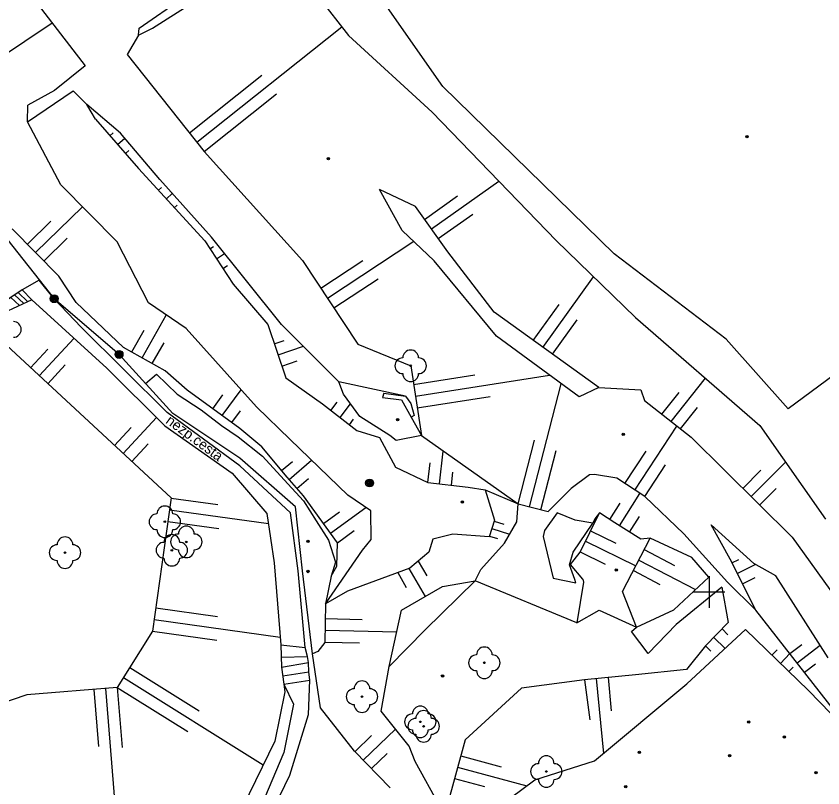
# Model space of a CAD drawing. Extents: x -639440 to -639026, y -1138850 to -1138262.
# Drawn here: x -639294 to -639242.8, y -1138562.4 to -1138513.4 of the extents above; entities that cross this region are included whole.
import ezdxf

# ---------------------------------------------------------------- set-up
doc = ezdxf.new("R2010")
doc.units = 0
for name, color, linetype in [('Vrstva 10', 7, 'Continuous'), ('Vrstva 11', 7, 'Continuous'), ('Vrstva 14', 7, 'Continuous'), ('Vrstva 15', 7, 'Continuous'), ('Vrstva 20', 7, 'Continuous'), ('Vrstva 22', 7, 'Continuous'), ('Vrstva 25', 7, 'Continuous'), ('Vrstva 40', 7, 'Continuous'), ('Vrstva 61', 7, 'Continuous'), ('Vrstva 7', 7, 'Continuous')]:
    doc.layers.add(name, color=color, linetype=linetype)

msp = doc.modelspace()

# ---------------------------------------------------------------- linework, layer by layer
at = {"layer": 'Vrstva 10'}
for p, q in [((-639266.91, -1138517.88), (-639273.38, -1138508.61)), ((-639256.02, -1138528.51), (-639266.91, -1138517.88)), ((-639248.91, -1138533.93), (-639256.02, -1138528.51)), ((-639244.97, -1138538.36), (-639248.91, -1138533.93)), ((-639239.11, -1138534.01), (-639244.97, -1138538.36))]:
    msp.add_line(p, q, dxfattribs=at)
at = {"layer": 'Vrstva 11'}
for p, q in [((-639286.2, -1138514.18), (-639283.12, -1138512.04)), ((-639285.35, -1138514.18), (-639282.84, -1138512.59)), ((-639286.24, -1138514.62), (-639285.35, -1138514.18)), ((-639286.24, -1138514.62), (-639286.2, -1138514.18)), ((-639289.62, -1138516.58), (-639291.57, -1138518.14)), ((-639291.57, -1138518.14), (-639293.27, -1138519.07)), ((-639288.97, -1138519.97), (-639289.51, -1138519.03)), ((-639287.37, -1138520.85), (-639289.51, -1138519.03)), ((-639284.89, -1138523.8), (-639287.37, -1138520.85)), ((-639281.6, -1138527.46), (-639284.89, -1138523.8)), ((-639291.3, -1138529.94), (-639294.25, -1138526.93)), ((-639277.16, -1138533), (-639281.6, -1138527.46)), ((-639292.54, -1138530.2), (-639293.63, -1138530.81)), ((-639291.59, -1138531.37), (-639292.54, -1138530.2)), ((-639290.2, -1138531.6), (-639291.3, -1138529.94)), ((-639293.63, -1138530.81), (-639295.29, -1138531.92)), ((-639294.104, -1138531.127), (-639293.523, -1138531.683)), ((-639293.261, -1138531.561), (-639293.867, -1138530.969)), ((-639293.63, -1138530.81), (-639293, -1138531.44)), ((-639293, -1138531.44), (-639294.83, -1138532.29)), ((-639293.784, -1138531.804), (-639294.341, -1138531.286)), ((-639289.87, -1138533.18), (-639291.59, -1138531.37)), ((-639287.18, -1138534.46), (-639290.2, -1138531.6)), ((-639284.41, -1138538.6), (-639289.87, -1138533.18)), ((-639273.52, -1138536.64), (-639277.16, -1138533)), ((-639284.54, -1138535.96), (-639287.18, -1138534.46)), ((-639283.14, -1138537.18), (-639284.54, -1138535.96)), ((-639279.8, -1138539.61), (-639283.14, -1138537.18)), ((-639270.66, -1138537.38), (-639270.75, -1138537.64)), ((-639270.66, -1138537.38), (-639269.29, -1138537.57)), ((-639270.75, -1138537.64), (-639269.54, -1138537.8)), ((-639269.54, -1138537.8), (-639268.91, -1138538.9)), ((-639269.29, -1138537.57), (-639268.94, -1138538.03)), ((-639268.94, -1138538.03), (-639268.72, -1138538.78)), ((-639279.8, -1138541.99), (-639284.41, -1138538.6)), ((-639268.72, -1138538.78), (-639268.91, -1138538.9)), ((-639268.91, -1138538.9), (-639268.26, -1138540.07)), ((-639278.41, -1138540.78), (-639279.8, -1138539.61)), ((-639276.8, -1138542.7), (-639278.41, -1138540.78)), ((-639276.59, -1138544.97), (-639279.8, -1138541.99)), ((-639275.76, -1138543.9), (-639276.8, -1138542.7)), ((-639273.6, -1138546.87), (-639275.76, -1138543.9)), ((-639276.09, -1138548.66), (-639276.59, -1138544.97)), ((-639258.19, -1138547.47), (-639256.97, -1138544.97)), ((-639273.64, -1138548.37), (-639273.6, -1138546.87)), ((-639258.81, -1138548.26), (-639258.19, -1138547.47)), ((-639275.66, -1138553.52), (-639276.09, -1138548.66)), ((-639273.99, -1138549), (-639273.64, -1138548.37)), ((-639258.02, -1138549.18), (-639258.81, -1138548.26)), ((-639249.19, -1138549.7), (-639252.09, -1138552.07)), ((-639254.93, -1138552.52), (-639254.62, -1138552.23)), ((-639252.09, -1138552.07), (-639253.86, -1138553.9)), ((-639253.86, -1138553.9), (-639254.93, -1138552.52)), ((-639277.19, -1138553.36), (-639275.66, -1138553.52)), ((-639277.19, -1138553.36), (-639277.16, -1138554.78)), ((-639275.51, -1138554.1), (-639275.66, -1138553.52)), ((-639277.174, -1138554.135), (-639275.51, -1138554.1)), ((-639275.44, -1138554.48), (-639275.51, -1138554.1)), ((-639277.16, -1138554.78), (-639275.44, -1138554.48)), ((-639277.16, -1138554.78), (-639277, -1138555.85)), ((-639275.42, -1138555.08), (-639275.44, -1138554.48)), ((-639277.078, -1138555.328), (-639275.42, -1138555.08)), ((-639275.36, -1138555.6), (-639275.42, -1138555.08)), ((-639277, -1138555.85), (-639275.36, -1138555.6)), ((-639277, -1138555.85), (-639276.39, -1138557.12)), ((-639275.43, -1138557.79), (-639275.36, -1138555.6)), ((-639276.39, -1138557.12), (-639277.01, -1138560.2)), ((-639276.62, -1138561.65), (-639275.43, -1138557.79)), ((-639277.01, -1138560.2), (-639278.62, -1138563.99)), ((-639278.5, -1138565.48), (-639276.62, -1138561.65))]:
    msp.add_line(p, q, dxfattribs=at)
at = {"layer": 'Vrstva 14'}
for p, q in [((-639277.59, -1138508.58), (-639272.91, -1138514.64)), ((-639293.74, -1138511.22), (-639289.62, -1138516.58)), ((-639286.24, -1138514.62), (-639286.96, -1138515.86)), ((-639272.91, -1138514.64), (-639267.58, -1138519.51)), ((-639286.96, -1138515.86), (-639282.07, -1138522.01)), ((-639293.29, -1138520.13), (-639290.39, -1138518.17)), ((-639290.39, -1138518.17), (-639289.51, -1138519.03)), ((-639293.29, -1138520.13), (-639293.27, -1138519.07)), ((-639288.97, -1138519.97), (-639286.24, -1138523.09)), ((-639267.58, -1138519.51), (-639259.71, -1138527.66)), ((-639291.17, -1138524.14), (-639293.29, -1138520.13)), ((-639282.07, -1138522.01), (-639275.81, -1138528.94)), ((-639286.24, -1138523.09), (-639282.03, -1138527.7)), ((-639287.59, -1138527.75), (-639291.17, -1138524.14)), ((-639268.65, -1138525.51), (-639270.94, -1138524.44)), ((-639269.49, -1138527.03), (-639270.94, -1138524.44)), ((-639266.6, -1138528.4), (-639268.65, -1138525.51)), ((-639267.45, -1138528.97), (-639269.49, -1138527.03)), ((-639259.71, -1138527.66), (-639254.67, -1138532.57)), ((-639285.61, -1138531.64), (-639287.59, -1138527.75)), ((-639282.03, -1138527.7), (-639280.22, -1138530.44)), ((-639263.66, -1138532.23), (-639266.6, -1138528.4)), ((-639275.81, -1138528.94), (-639272.31, -1138534.26)), ((-639263.5, -1138533.75), (-639267.45, -1138528.97)), ((-639280.22, -1138530.44), (-639278.03, -1138533.01)), ((-639293, -1138531.44), (-639288.24, -1138535.79)), ((-639283.2, -1138533.27), (-639285.61, -1138531.64)), ((-639257.01, -1138537.02), (-639263.66, -1138532.23)), ((-639296.56, -1138532.54), (-639284.16, -1138544.03)), ((-639254.67, -1138532.57), (-639246.79, -1138539.42)), ((-639278.75, -1138538.24), (-639283.2, -1138533.27)), ((-639278.03, -1138533.01), (-639276.87, -1138536.4)), ((-639258.25, -1138537.61), (-639263.5, -1138533.75)), ((-639272.31, -1138534.26), (-639268.95, -1138535.63)), ((-639288.24, -1138535.79), (-639284.57, -1138539.45)), ((-639268.95, -1138535.63), (-639268.26, -1138540.07)), ((-639285.78, -1138536.76), (-639285.1, -1138536.17)), ((-639285.1, -1138536.17), (-639283.77, -1138537.44)), ((-639276.87, -1138536.4), (-639274.56, -1138538.05)), ((-639269.29, -1138537.57), (-639273.52, -1138536.64)), ((-639273.22, -1138537.43), (-639273.52, -1138536.64)), ((-639257.01, -1138537.02), (-639258.25, -1138537.61)), ((-639257.01, -1138537.02), (-639254.34, -1138537.15)), ((-639254.34, -1138537.15), (-639254.1, -1138537.84)), ((-639283.77, -1138537.44), (-639282.26, -1138538.42)), ((-639272.18, -1138538.85), (-639273.22, -1138537.43)), ((-639254.1, -1138537.84), (-639251.15, -1138540.17)), ((-639282.26, -1138538.42), (-639280.96, -1138539.42)), ((-639276.61, -1138540.31), (-639278.75, -1138538.24)), ((-639274.56, -1138538.05), (-639272.36, -1138539.75)), ((-639270.27, -1138540.06), (-639272.18, -1138538.85)), ((-639284.57, -1138539.45), (-639280.28, -1138542.45)), ((-639280.96, -1138539.42), (-639279.91, -1138540.14)), ((-639246.79, -1138539.42), (-639242.6, -1138545.37)), ((-639272.36, -1138539.75), (-639270.94, -1138540.18)), ((-639279.91, -1138540.14), (-639278.37, -1138541.38)), ((-639272.95, -1138543.85), (-639276.61, -1138540.31)), ((-639270.94, -1138540.18), (-639269.92, -1138542.08)), ((-639269.88, -1138540.37), (-639270.27, -1138540.06)), ((-639268.26, -1138540.07), (-639269.88, -1138540.37)), ((-639268.26, -1138540.07), (-639262.13, -1138544.4)), ((-639251.15, -1138540.17), (-639244.72, -1138546.51)), ((-639278.37, -1138541.38), (-639276.99, -1138542.87)), ((-639280.28, -1138542.45), (-639278.08, -1138545.02)), ((-639269.92, -1138542.08), (-639267.86, -1138543.05)), ((-639257.27, -1138542.53), (-639257.59, -1138542.55)), ((-639255.86, -1138542.78), (-639257.27, -1138542.53)), ((-639276.99, -1138542.87), (-639275.75, -1138544.22)), ((-639257.59, -1138542.55), (-639258.77, -1138543.42)), ((-639254.09, -1138543.94), (-639255.86, -1138542.78)), ((-639267.86, -1138543.05), (-639265.29, -1138543.34)), ((-639265.29, -1138543.34), (-639264.23, -1138543.52)), ((-639264.23, -1138543.52), (-639262.13, -1138544.4)), ((-639264.23, -1138543.52), (-639263.63, -1138545.43)), ((-639258.77, -1138543.42), (-639260.23, -1138544.89)), ((-639284.16, -1138544.03), (-639285.34, -1138552.49)), ((-639271.48, -1138544.84), (-639272.95, -1138543.85)), ((-639251.61, -1138546.3), (-639254.09, -1138543.94)), ((-639275.75, -1138544.22), (-639274.96, -1138545.48)), ((-639262.22, -1138545.55), (-639262.13, -1138544.4)), ((-639262.13, -1138544.4), (-639260.23, -1138544.89)), ((-639278.08, -1138545.02), (-639277.63, -1138548.14)), ((-639271.45, -1138546.67), (-639271.48, -1138544.84)), ((-639259.64, -1138544.97), (-639260.45, -1138546.1)), ((-639258.5, -1138545.44), (-639259.64, -1138544.97)), ((-639256.97, -1138544.97), (-639257.26, -1138545.35)), ((-639255.99, -1138545.6), (-639256.97, -1138544.97)), ((-639274.96, -1138545.48), (-639274.18, -1138546.7)), ((-639263.63, -1138545.43), (-639263.97, -1138546.5)), ((-639263, -1138546.9), (-639262.22, -1138545.55)), ((-639257.39, -1138545.62), (-639258.5, -1138545.44)), ((-639257.26, -1138545.35), (-639257.39, -1138545.62)), ((-639254.34, -1138546.64), (-639255.99, -1138545.6)), ((-639260.45, -1138546.1), (-639260.53, -1138546.47)), ((-639258.63, -1138547.47), (-639257.39, -1138545.62)), ((-639247.17, -1138548.19), (-639249.87, -1138545.73)), ((-639248.67, -1138547.92), (-639249.87, -1138545.73)), ((-639266.27, -1138546.33), (-639267.54, -1138546.65)), ((-639263.97, -1138546.5), (-639266.27, -1138546.33)), ((-639260.53, -1138546.47), (-639259.9, -1138549.12)), ((-639255.5, -1138549.97), (-639253.74, -1138546.59)), ((-639253.74, -1138546.59), (-639254.34, -1138546.64)), ((-639251.09, -1138547.82), (-639253.74, -1138546.59)), ((-639248.83, -1138549.37), (-639251.61, -1138546.3)), ((-639244.72, -1138546.51), (-639240.23, -1138552.81)), ((-639274.18, -1138546.7), (-639273.73, -1138548.11)), ((-639272, -1138547.35), (-639271.45, -1138546.67)), ((-639267.54, -1138546.65), (-639267.8, -1138547.48)), ((-639264.49, -1138548.58), (-639263, -1138546.9)), ((-639274.35, -1138550.75), (-639272, -1138547.35)), ((-639267.8, -1138547.48), (-639269, -1138548.49)), ((-639258.87, -1138548.27), (-639258.63, -1138547.47)), ((-639277.63, -1138548.14), (-639277.19, -1138553.36)), ((-639273.73, -1138548.11), (-639273.99, -1138549)), ((-639250.02, -1138549.07), (-639251.09, -1138547.82)), ((-639247.03, -1138551.15), (-639248.67, -1138547.92)), ((-639269, -1138548.49), (-639272.96, -1138549.94)), ((-639264.85, -1138549.3), (-639264.49, -1138548.58)), ((-639258.52, -1138549.21), (-639258.87, -1138548.27)), ((-639245.76, -1138548.98), (-639247.17, -1138548.19)), ((-639273.99, -1138549), (-639274.35, -1138550.75)), ((-639259.9, -1138549.12), (-639258.46, -1138549.41)), ((-639258.02, -1138549.18), (-639257.97, -1138549.38)), ((-639252.23, -1138551.14), (-639250.02, -1138549.07)), ((-639242.44, -1138554.18), (-639245.76, -1138548.98)), ((-639269.54, -1138551.16), (-639266.93, -1138549.65)), ((-639268.03, -1138552.41), (-639264.85, -1138549.3)), ((-639266.93, -1138549.65), (-639264.85, -1138549.3)), ((-639258.39, -1138551.97), (-639264.85, -1138549.3)), ((-639258.46, -1138549.41), (-639258.52, -1138549.21)), ((-639257.97, -1138549.38), (-639258.39, -1138551.97)), ((-639249.19, -1138549.7), (-639248.78, -1138551.95)), ((-639247.03, -1138551.15), (-639248.83, -1138549.37)), ((-639272.96, -1138549.94), (-639274.35, -1138550.75)), ((-639254.62, -1138552.23), (-639255.5, -1138549.97)), ((-639274.35, -1138550.75), (-639274.41, -1138553.22)), ((-639270.31, -1138554.73), (-639269.54, -1138551.16)), ((-639258.39, -1138551.97), (-639256.98, -1138551.16)), ((-639256.98, -1138551.16), (-639254.62, -1138552.23)), ((-639254.62, -1138552.23), (-639252.23, -1138551.14)), ((-639240.47, -1138559.58), (-639247.03, -1138551.15)), ((-639248.78, -1138551.95), (-639250.23, -1138553.42)), ((-639285.34, -1138552.49), (-639287.58, -1138556.07)), ((-639270.31, -1138554.73), (-639268.03, -1138552.41)), ((-639251.41, -1138555.84), (-639247.68, -1138552.39)), ((-639247.68, -1138552.39), (-639243.69, -1138556.27)), ((-639274.41, -1138553.22), (-639274.84, -1138553.78)), ((-639274.84, -1138553.78), (-639275.18, -1138553.93)), ((-639250.23, -1138553.42), (-639251.43, -1138554.93)), ((-639270.83, -1138557.57), (-639270.31, -1138554.73)), ((-639254.67, -1138555.27), (-639257.91, -1138555.58)), ((-639251.43, -1138554.93), (-639254.67, -1138555.27)), ((-639277, -1138555.85), (-639276.95, -1138556.35)), ((-639257.91, -1138555.58), (-639261.92, -1138556.12)), ((-639257.28, -1138560.73), (-639251.41, -1138555.84)), ((-639287.58, -1138556.07), (-639293.32, -1138556.53)), ((-639276.95, -1138556.35), (-639277.58, -1138559.48)), ((-639261.92, -1138556.12), (-639265.5, -1138559.4)), ((-639243.69, -1138556.27), (-639240.47, -1138559.58)), ((-639293.32, -1138556.53), (-639301.59, -1138559.4)), ((-639269.05, -1138559.79), (-639270.83, -1138557.57)), ((-639265.5, -1138559.4), (-639266.8, -1138564.16)), ((-639277.58, -1138559.48), (-639279.72, -1138563.89)), ((-639268.66, -1138560.77), (-639269.05, -1138559.79)), ((-639266.8, -1138564.16), (-639268.66, -1138560.77)), ((-639261.06, -1138561.94), (-639257.28, -1138560.73)), ((-639263.82, -1138563.96), (-639261.06, -1138561.94))]:
    msp.add_line(p, q, dxfattribs=at)
at = {"layer": 'Vrstva 15'}
for p, q in [((-639299.041, -1138518.762), (-639291.724, -1138513.843)), ((-639282.537, -1138521.423), (-639273.327, -1138514.1)), ((-639283.004, -1138520.836), (-639278.394, -1138517.171)), ((-639282.07, -1138522.01), (-639277.465, -1138518.348)), ((-639288.054, -1138521.017), (-639287.837, -1138520.827)), ((-639287.56, -1138521.581), (-639287.096, -1138521.175)), ((-639287.066, -1138522.146), (-639286.84, -1138521.948)), ((-639267.636, -1138526.939), (-639263.345, -1138523.895)), ((-639284.971, -1138524.479), (-639284.781, -1138524.306)), ((-639284.466, -1138525.033), (-639284.09, -1138524.69)), ((-639268.07, -1138526.327), (-639265.971, -1138524.838)), ((-639292.767, -1138528.443), (-639289.793, -1138525.528)), ((-639283.96, -1138525.587), (-639283.774, -1138525.417)), ((-639267.202, -1138527.551), (-639265.01, -1138525.996)), ((-639293.292, -1138527.907), (-639291.807, -1138526.451)), ((-639292.242, -1138528.978), (-639290.754, -1138527.52)), ((-639281.7, -1138528.199), (-639281.474, -1138528.05)), ((-639274.24, -1138531.327), (-639268.761, -1138527.723)), ((-639281.287, -1138528.825), (-639280.776, -1138528.488)), ((-639274.652, -1138530.7), (-639271.986, -1138528.946)), ((-639280.874, -1138529.451), (-639280.589, -1138529.263)), ((-639273.827, -1138531.954), (-639271.015, -1138530.104)), ((-639260.563, -1138534.461), (-639257.333, -1138529.976)), ((-639261.172, -1138534.022), (-639259.524, -1138531.734)), ((-639286.011, -1138535.124), (-639284.469, -1138532.412)), ((-639259.955, -1138534.899), (-639258.372, -1138532.702)), ((-639286.663, -1138534.754), (-639285.878, -1138533.372)), ((-639292.54, -1138536.265), (-639290.33, -1138533.88)), ((-639285.359, -1138535.495), (-639284.602, -1138534.164)), ((-639277.612, -1138534.232), (-639276.984, -1138534.018)), ((-639293.091, -1138535.755), (-639291.987, -1138534.564)), ((-639277.369, -1138534.942), (-639275.767, -1138534.393)), ((-639277.126, -1138535.651), (-639276.151, -1138535.318)), ((-639291.99, -1138536.774), (-639290.883, -1138535.58)), ((-639268.766, -1138536.812), (-639264.873, -1138536.207)), ((-639268.651, -1138537.553), (-639260.128, -1138536.229)), ((-639261.404, -1138544.587), (-639259.388, -1138536.773)), ((-639252.41, -1138539.175), (-639250.237, -1138536.423)), ((-639280.916, -1138538.798), (-639279.721, -1138537.156)), ((-639252.999, -1138538.71), (-639251.901, -1138537.32)), ((-639281.522, -1138538.357), (-639280.877, -1138537.471)), ((-639268.536, -1138538.295), (-639263.906, -1138537.575)), ((-639274.027, -1138538.462), (-639273.625, -1138537.942)), ((-639273.434, -1138538.92), (-639272.764, -1138538.053)), ((-639251.822, -1138539.64), (-639250.746, -1138538.278)), ((-639287.214, -1138541.2), (-639285.101, -1138538.92)), ((-639280.309, -1138539.239), (-639279.759, -1138538.483)), ((-639272.841, -1138539.379), (-639272.572, -1138539.031)), ((-639254.718, -1138543.529), (-639252.05, -1138539.459)), ((-639287.764, -1138540.691), (-639286.698, -1138539.541)), ((-639262.13, -1138544.4), (-639261.085, -1138540.347)), ((-639286.663, -1138541.71), (-639285.616, -1138540.58)), ((-639267.114, -1138543.134), (-639266.878, -1138541.046)), ((-639260.677, -1138544.775), (-639259.707, -1138541.013)), ((-639255.345, -1138543.118), (-639253.993, -1138541.055)), ((-639277.152, -1138542.28), (-639276.462, -1138541.701)), ((-639276.668, -1138542.852), (-639275.251, -1138541.624)), ((-639267.859, -1138543.05), (-639267.718, -1138541.801)), ((-639254.09, -1138543.94), (-639252.775, -1138541.933)), ((-639247.322, -1138543.945), (-639245.153, -1138541.745)), ((-639266.369, -1138543.218), (-639266.274, -1138542.379)), ((-639247.856, -1138543.418), (-639246.724, -1138542.27)), ((-639276.177, -1138543.419), (-639275.443, -1138542.783)), ((-639246.788, -1138544.471), (-639245.751, -1138543.42)), ((-639284.16, -1138544.031), (-639281.189, -1138544.445)), ((-639255.682, -1138545.794), (-639254.389, -1138543.744)), ((-639256.314, -1138545.392), (-639255.656, -1138544.368)), ((-639284.264, -1138544.774), (-639277.989, -1138545.649)), ((-639274.483, -1138545.656), (-639273.469, -1138544.919)), ((-639274.042, -1138546.263), (-639271.794, -1138544.628)), ((-639284.367, -1138545.517), (-639281.123, -1138545.969)), ((-639263.65, -1138545.493), (-639263.032, -1138545.689)), ((-639255.047, -1138546.194), (-639254.424, -1138545.205)), ((-639273.6, -1138546.869), (-639272.536, -1138546.095)), ((-639263.801, -1138545.969), (-639262.67, -1138546.329)), ((-639257.525, -1138546.107), (-639255.915, -1138546.892)), ((-639263.953, -1138546.446), (-639263.439, -1138546.609)), ((-639257.854, -1138546.781), (-639254.653, -1138548.343)), ((-639258.182, -1138547.455), (-639256.591, -1138548.231)), ((-639254.115, -1138547.309), (-639252.195, -1138548.309)), ((-639268.466, -1138548.04), (-639267.924, -1138548.976)), ((-639254.461, -1138547.975), (-639250.855, -1138549.852)), ((-639248.55, -1138548.156), (-639248.119, -1138547.937)), ((-639269.06, -1138548.512), (-639268.032, -1138550.288)), ((-639254.807, -1138548.64), (-639253.121, -1138549.518)), ((-639248.211, -1138548.825), (-639247.071, -1138548.246)), ((-639269.775, -1138548.774), (-639269.228, -1138549.718)), ((-639247.871, -1138549.493), (-639247.077, -1138549.09)), ((-639285.133, -1138551.004), (-639281.215, -1138551.551)), ((-639285.236, -1138551.747), (-639277.232, -1138552.864)), ((-639274.373, -1138551.684), (-639272.025, -1138551.741)), ((-639285.34, -1138552.49), (-639281.262, -1138553.059)), ((-639274.391, -1138552.434), (-639269.839, -1138552.544)), ((-639249.177, -1138552.352), (-639248.805, -1138552.719)), ((-639274.409, -1138553.183), (-639272.204, -1138553.237)), ((-639249.703, -1138552.886), (-639248.984, -1138553.596)), ((-639250.23, -1138553.42), (-639249.882, -1138553.763)), ((-639246.011, -1138554.013), (-639245.675, -1138553.668)), ((-639244.875, -1138553.92), (-639244.117, -1138553.33)), ((-639244.414, -1138554.512), (-639242.954, -1138553.375)), ((-639245.473, -1138554.536), (-639244.874, -1138553.92)), ((-639286.784, -1138554.798), (-639282.383, -1138557.553)), ((-639244.936, -1138555.059), (-639244.673, -1138554.788)), ((-639243.953, -1138555.104), (-639243.251, -1138554.557)), ((-639287.182, -1138555.434), (-639278.31, -1138560.985)), ((-639257.911, -1138555.58), (-639257.567, -1138558.132)), ((-639257.164, -1138555.509), (-639256.71, -1138560.255)), ((-639256.418, -1138555.437), (-639256.215, -1138557.556)), ((-639289.075, -1138556.19), (-639288.784, -1138559.827)), ((-639288.328, -1138556.13), (-639287.738, -1138563.493)), ((-639287.58, -1138556.07), (-639283.11, -1138558.867)), ((-639287.58, -1138556.07), (-639287.274, -1138559.884)), ((-639271.96, -1138560.68), (-639269.918, -1138558.708)), ((-639272.481, -1138560.14), (-639271.435, -1138559.13)), ((-639271.438, -1138561.219), (-639270.442, -1138560.257)), ((-639265.774, -1138560.403), (-639263.206, -1138561.104)), ((-639265.971, -1138561.126), (-639261.585, -1138562.324)), ((-639266.169, -1138561.85), (-639264.264, -1138562.37))]:
    msp.add_line(p, q, dxfattribs=at)
at = {"layer": 'Vrstva 20'}
for centre, radius in [((-639247.6, -1138521.08), 0.075), ((-639247.6, -1138521.08), 0.0204), ((-639274.18, -1138522.47), 0.075), ((-639274.18, -1138522.47), 0.0204), ((-639269.78, -1138539.06), 0.075), ((-639269.78, -1138539.06), 0.0204), ((-639255.45, -1138539.99), 0.075), ((-639255.45, -1138539.99), 0.0204), ((-639265.67, -1138544.29), 0.075), ((-639265.67, -1138544.29), 0.0204), ((-639275.48, -1138546.79), 0.075), ((-639275.48, -1138546.79), 0.0204), ((-639275.48, -1138548.7), 0.075), ((-639275.48, -1138548.7), 0.0204), ((-639255.9, -1138548.6), 0.075), ((-639255.9, -1138548.6), 0.0204), ((-639266.93, -1138555.34), 0.075), ((-639266.93, -1138555.34), 0.0204), ((-639247.48, -1138558.27), 0.075), ((-639247.48, -1138558.27), 0.0204), ((-639245.22, -1138559.22), 0.075), ((-639245.22, -1138559.22), 0.0204), ((-639254.43, -1138560.19), 0.075), ((-639254.43, -1138560.19), 0.0204), ((-639248.7, -1138560.41), 0.075), ((-639248.7, -1138560.41), 0.0204), ((-639243.21, -1138561.49), 0.075), ((-639243.21, -1138561.49), 0.0204), ((-639255.29, -1138562.37), 0.075), ((-639255.29, -1138562.37), 0.0204)]:
    msp.add_circle(centre, radius, dxfattribs=at)
at = {"layer": 'Vrstva 22'}
for centre in [(-639268.95, -1138535.63), (-639284.56, -1138545.54), (-639283.2, -1138546.82), (-639290.9, -1138547.5), (-639284.12, -1138547.35), (-639264.27, -1138554.5), (-639272.04, -1138556.65), (-639268.34, -1138558.25), (-639268.13, -1138558.54), (-639260.34, -1138561.41)]:
    msp.add_circle(centre, 0.05, dxfattribs=at)
for centre, start, end in [((-639294.18, -1138533.32), 270, 90), ((-639268.95, -1138535.13), 0, 180), ((-639269.45, -1138535.63), 90, 270), ((-639268.45, -1138535.63), 270, 90), ((-639268.95, -1138536.13), 180, 0), ((-639284.56, -1138545.04), 0, 180), ((-639285.06, -1138545.54), 90, 270), ((-639284.06, -1138545.54), 270, 90), ((-639284.56, -1138546.04), 180, 0), ((-639283.2, -1138546.32), 0, 180), ((-639290.9, -1138547), 0, 180), ((-639284.12, -1138546.85), 0, 180), ((-639283.7, -1138546.82), 90, 270), ((-639282.7, -1138546.82), 270, 90), ((-639291.4, -1138547.5), 90, 270), ((-639290.4, -1138547.5), 270, 90), ((-639284.62, -1138547.35), 90, 270), ((-639283.62, -1138547.35), 270, 90), ((-639283.2, -1138547.32), 180, 0), ((-639290.9, -1138548), 180, 0), ((-639284.12, -1138547.85), 180, 0), ((-639264.27, -1138554), 0, 180), ((-639264.77, -1138554.5), 90, 270), ((-639263.77, -1138554.5), 270, 90), ((-639264.27, -1138555), 180, 0), ((-639272.04, -1138556.15), 0, 180), ((-639272.54, -1138556.65), 90, 270), ((-639271.54, -1138556.65), 270, 90), ((-639272.04, -1138557.15), 180, 0), ((-639268.34, -1138557.75), 0, 180), ((-639268.84, -1138558.25), 90, 270), ((-639268.13, -1138558.04), 0, 180), ((-639267.84, -1138558.25), 270, 90), ((-639268.63, -1138558.54), 90, 270), ((-639267.63, -1138558.54), 270, 90), ((-639268.34, -1138558.75), 180, 0), ((-639268.13, -1138559.04), 180, 0), ((-639260.34, -1138560.91), 0, 180), ((-639260.84, -1138561.41), 90, 270), ((-639259.84, -1138561.41), 270, 90), ((-639260.34, -1138561.91), 180, 0)]:
    msp.add_arc(centre, 0.5, start, end, dxfattribs=at)
at = {"layer": 'Vrstva 25'}
for centre, radius in [((-639291.59, -1138531.37), 0.25), ((-639291.59, -1138531.37), 0.2), ((-639291.59, -1138531.37), 0.15), ((-639291.59, -1138531.37), 0.1), ((-639291.59, -1138531.37), 0.05), ((-639287.47, -1138534.91), 0.25), ((-639287.47, -1138534.91), 0.2), ((-639287.47, -1138534.91), 0.15), ((-639287.47, -1138534.91), 0.1), ((-639287.47, -1138534.91), 0.05), ((-639271.56, -1138543.08), 0.25), ((-639271.56, -1138543.08), 0.2), ((-639271.56, -1138543.08), 0.15), ((-639271.56, -1138543.08), 0.1), ((-639271.56, -1138543.08), 0.05)]:
    msp.add_circle(centre, radius, dxfattribs=at)
at = {"layer": 'Vrstva 61'}
for p, q in [((-639250, -1138549), (-639250, -1138551)), ((-639251, -1138550), (-639249, -1138550))]:
    msp.add_line(p, q, dxfattribs=at)
at = {"layer": 'Vrstva 7'}
for p, q in [((-639294.84, -1138527.24), (-639291.59, -1138531.37)), ((-639287.47, -1138534.91), (-639291.59, -1138531.37)), ((-639284.06, -1138538.66), (-639287.47, -1138534.91)), ((-639279.81, -1138541.5), (-639284.06, -1138538.66)), ((-639276.26, -1138544.59), (-639279.81, -1138541.5)), ((-639275.81, -1138548.65), (-639276.26, -1138544.59)), ((-639275.18, -1138553.93), (-639275.81, -1138548.65)), ((-639274.68, -1138557.37), (-639275.18, -1138553.93)), ((-639272.51, -1138560.11), (-639274.68, -1138557.37)), ((-639270.25, -1138562.45), (-639272.51, -1138560.11))]:
    msp.add_line(p, q, dxfattribs=at)

# ---------------------------------------------------------------- texts
at = {"layer": 'Vrstva 40'}
msp.add_text('nezp.cesta', height=0.65, rotation=323.6708, dxfattribs=at).set_placement((-639284.556, -1138539.235))

doc.saveas('drawing.dxf')
